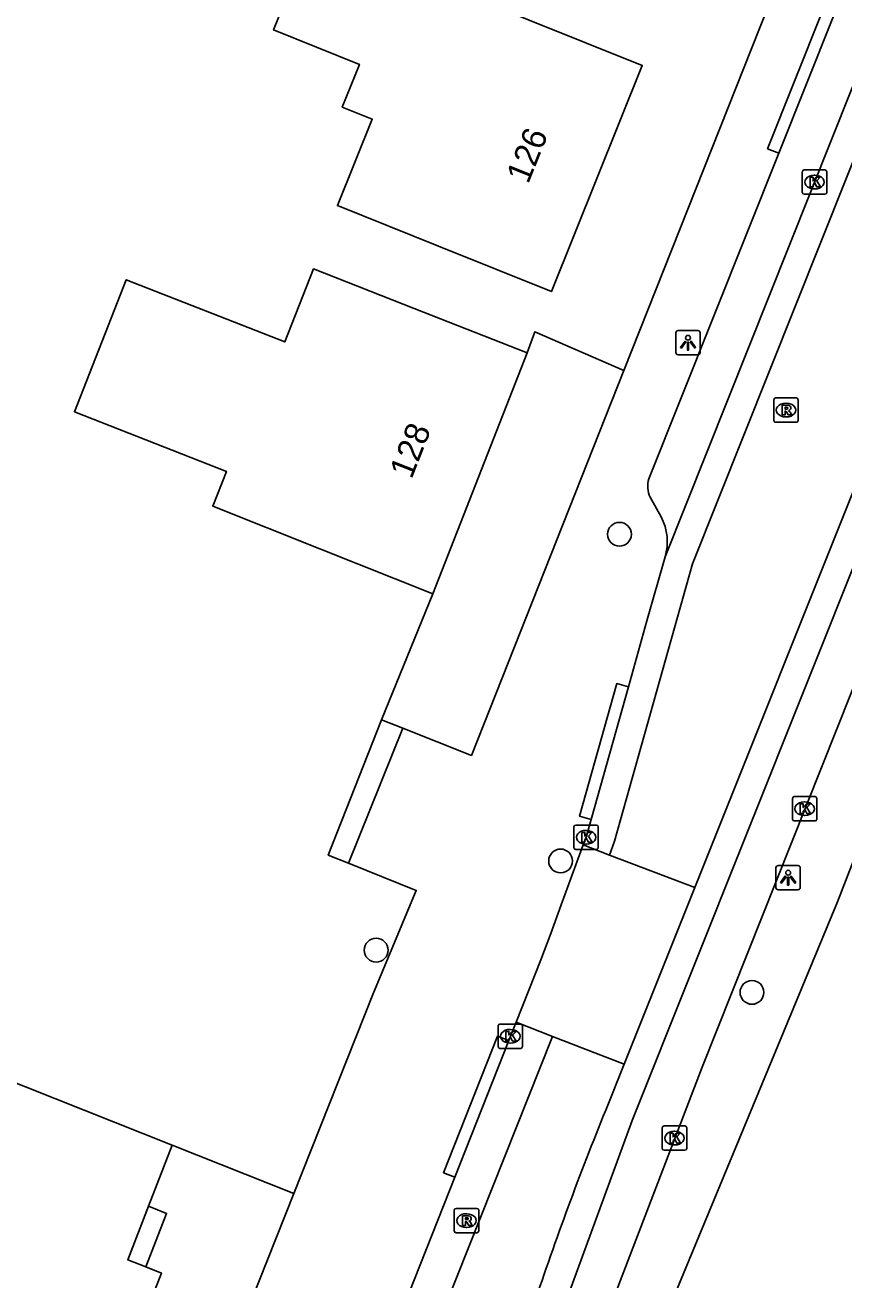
# Model space of a CAD drawing. Extents: x 160026 to 161302, y 384757 to 385701.
# Drawn here: x 160361.4 to 160395, y 384880.6 to 384932.1 of the extents above; entities that cross this region are included whole.
import ezdxf

# ---------------------------------------------------------------- set-up
doc = ezdxf.new("R2010")
doc.units = 0
for name, color, linetype in [('IMGEO_Boom', 7, 'Continuous'), ('IMGEO_Groenvoorziening', 7, 'Continuous'), ('IMGEO_Kolk', 7, 'Continuous'), ('IMGEO_Lichtpunt', 7, 'Continuous'), ('IMGEO_Pand', 7, 'Continuous'), ('IMGEO_Pand_nummerreeks', 7, 'Continuous'), ('IMGEO_Rijbaan_lokaal_open', 7, 'Continuous'), ('IMGEO_Rioolput', 7, 'Continuous'), ('IMGEO_Voetpad_open', 7, 'Continuous')]:
    doc.layers.add(name, color=color, linetype=linetype)

msp = doc.modelspace()

# ---------------------------------------------------------------- linework, layer by layer
at = {"layer": 'IMGEO_Boom'}
for centre in [(160385.821, 384911.173), (160383.404, 384897.757), (160375.826, 384894.095), (160391.266, 384892.363)]:
    msp.add_circle(centre, 0.489, dxfattribs=at)
at = {"layer": 'IMGEO_Groenvoorziening'}
for points in [[(160374.691, 384897.666), (160373.861, 384897.999), (160376.039, 384903.56)], [(160367.44, 384886.086), (160372.439, 384884.099)], [(160366.473, 384883.584), (160367.215, 384883.283), (160366.365, 384881.086)]]:
    msp.add_lwpolyline(points, dxfattribs=at)
at = {"layer": 'IMGEO_Kolk'}
for p, q in [((160393.334, 384925.207), (160393.334, 384926.059)), ((160393.409, 384926.133), (160394.261, 384926.133)), ((160393.822, 384925.913), (160393.847, 384925.913)), ((160394.335, 384926.059), (160394.335, 384925.207)), ((160393.845, 384925.353), (160393.82, 384925.353)), ((160394.261, 384925.133), (160393.409, 384925.133)), ((160392.929, 384899.477), (160392.929, 384900.329)), ((160393.004, 384900.403), (160393.856, 384900.403)), ((160393.417, 384900.183), (160393.442, 384900.183)), ((160393.93, 384900.329), (160393.93, 384899.477)), ((160393.44, 384899.623), (160393.415, 384899.623)), ((160383.952, 384898.306), (160383.952, 384899.158)), ((160384.027, 384899.232), (160384.879, 384899.232)), ((160384.953, 384899.158), (160384.953, 384898.306)), ((160393.856, 384899.403), (160393.004, 384899.403)), ((160384.44, 384899.012), (160384.465, 384899.012)), ((160384.879, 384898.232), (160384.027, 384898.232)), ((160384.463, 384898.452), (160384.438, 384898.452)), ((160380.837, 384890.135), (160380.837, 384890.987)), ((160380.912, 384891.061), (160381.764, 384891.061)), ((160381.325, 384890.841), (160381.35, 384890.841)), ((160381.838, 384890.987), (160381.838, 384890.135)), ((160381.348, 384890.281), (160381.323, 384890.281)), ((160381.764, 384890.061), (160380.912, 384890.061)), ((160387.582, 384885.951), (160387.582, 384886.803)), ((160387.657, 384886.877), (160388.509, 384886.877)), ((160388.07, 384886.657), (160388.095, 384886.657)), ((160388.583, 384886.803), (160388.583, 384885.951)), ((160388.509, 384885.877), (160387.657, 384885.877)), ((160388.093, 384886.097), (160388.068, 384886.097))]:
    msp.add_line(p, q, dxfattribs=at)
for points in [[(160393.334, 384925.207), (160393.334, 384926.059)], [(160393.409, 384926.133), (160394.261, 384926.133)], [(160393.655, 384925.833), (160393.778, 384925.833), (160393.778, 384925.682), (160393.908, 384925.833), (160394.072, 384925.833), (160393.926, 384925.682), (160394.079, 384925.433), (160393.927, 384925.433), (160393.842, 384925.597), (160393.778, 384925.53), (160393.778, 384925.433), (160393.655, 384925.433), (160393.655, 384925.833)], [(160394.335, 384926.059), (160394.335, 384925.207)], [(160394.261, 384925.133), (160393.409, 384925.133)], [(160392.929, 384899.477), (160392.929, 384900.329)], [(160393.004, 384900.403), (160393.856, 384900.403)], [(160393.25, 384900.103), (160393.373, 384900.103), (160393.373, 384899.952), (160393.503, 384900.103), (160393.667, 384900.103), (160393.521, 384899.952), (160393.674, 384899.703), (160393.522, 384899.703), (160393.437, 384899.867), (160393.373, 384899.8), (160393.373, 384899.703), (160393.25, 384899.703), (160393.25, 384900.103)], [(160393.93, 384900.329), (160393.93, 384899.477)], [(160383.952, 384898.306), (160383.952, 384899.158)], [(160384.027, 384899.232), (160384.879, 384899.232)], [(160384.953, 384899.158), (160384.953, 384898.306)], [(160393.856, 384899.403), (160393.004, 384899.403)], [(160384.273, 384898.932), (160384.396, 384898.932), (160384.396, 384898.781), (160384.526, 384898.932), (160384.69, 384898.932), (160384.544, 384898.781), (160384.697, 384898.532), (160384.545, 384898.532), (160384.46, 384898.696), (160384.396, 384898.629), (160384.396, 384898.532), (160384.273, 384898.532), (160384.273, 384898.932)], [(160384.879, 384898.232), (160384.027, 384898.232)], [(160380.837, 384890.135), (160380.837, 384890.987)], [(160380.912, 384891.061), (160381.764, 384891.061)], [(160381.838, 384890.987), (160381.838, 384890.135)], [(160381.158, 384890.761), (160381.281, 384890.761), (160381.281, 384890.61), (160381.411, 384890.761), (160381.575, 384890.761), (160381.429, 384890.61), (160381.582, 384890.361), (160381.43, 384890.361), (160381.345, 384890.525), (160381.281, 384890.458), (160381.281, 384890.361), (160381.158, 384890.361), (160381.158, 384890.761)], [(160381.764, 384890.061), (160380.912, 384890.061)], [(160387.582, 384885.951), (160387.582, 384886.803)], [(160387.657, 384886.877), (160388.509, 384886.877)], [(160388.583, 384886.803), (160388.583, 384885.951)], [(160387.903, 384886.577), (160388.026, 384886.577), (160388.026, 384886.426), (160388.156, 384886.577), (160388.32, 384886.577), (160388.174, 384886.426), (160388.327, 384886.177), (160388.175, 384886.177), (160388.09, 384886.341), (160388.026, 384886.274), (160388.026, 384886.177), (160387.903, 384886.177), (160387.903, 384886.577)], [(160388.509, 384885.877), (160387.657, 384885.877)]]:
    msp.add_lwpolyline(points, dxfattribs=at)
for centre, start, end in [((160393.411, 384926.057), 91.552, 178.448), ((160393.411, 384926.057), 91.552, 178.448), ((160394.259, 384926.057), 1.552, 88.448), ((160394.259, 384926.057), 1.552, 88.448), ((160393.411, 384925.209), 181.552, 268.448), ((160393.411, 384925.209), 181.552, 268.448), ((160394.259, 384925.209), 271.552, 358.448), ((160394.259, 384925.209), 271.552, 358.448), ((160393.006, 384900.327), 91.552, 178.448), ((160393.006, 384900.327), 91.552, 178.448), ((160393.854, 384900.327), 1.552, 88.448), ((160393.854, 384900.327), 1.552, 88.448), ((160384.029, 384899.156), 91.552, 178.448), ((160384.029, 384899.156), 91.552, 178.448), ((160384.877, 384899.156), 1.552, 88.448), ((160384.877, 384899.156), 1.552, 88.448), ((160393.006, 384899.479), 181.552, 268.448), ((160393.006, 384899.479), 181.552, 268.448), ((160393.854, 384899.479), 271.552, 358.448), ((160393.854, 384899.479), 271.552, 358.448), ((160384.029, 384898.308), 181.552, 268.448), ((160384.029, 384898.308), 181.552, 268.448), ((160384.877, 384898.308), 271.552, 358.448), ((160384.877, 384898.308), 271.552, 358.448), ((160380.914, 384890.985), 91.552, 178.448), ((160380.914, 384890.985), 91.552, 178.448), ((160381.762, 384890.985), 1.552, 88.448), ((160381.762, 384890.985), 1.552, 88.448), ((160380.914, 384890.137), 181.552, 268.448), ((160380.914, 384890.137), 181.552, 268.448), ((160381.762, 384890.137), 271.552, 358.448), ((160381.762, 384890.137), 271.552, 358.448), ((160387.659, 384886.801), 91.552, 178.448), ((160387.659, 384886.801), 91.552, 178.448), ((160388.507, 384886.801), 1.552, 88.448), ((160388.507, 384886.801), 1.552, 88.448), ((160387.659, 384885.953), 181.552, 268.448), ((160387.659, 384885.953), 181.552, 268.448), ((160388.507, 384885.953), 271.552, 358.448), ((160388.507, 384885.953), 271.552, 358.448)]:
    msp.add_arc(centre, 0.0765, start, end, dxfattribs=at)
for centre, major_axis, ratio, start_param, end_param in [((160393.821, 384925.633), (-0.387, 0.002), 0.722429, 4.712389, 7.853982), ((160393.846, 384925.633), (-0.39, 0.002), 0.717154, 1.570796, 4.712389), ((160393.416, 384899.903), (-0.387, 0.002), 0.722429, 4.712389, 7.853982), ((160393.441, 384899.903), (-0.39, 0.002), 0.717154, 1.570796, 4.712389), ((160384.439, 384898.732), (-0.387, 0.002), 0.722429, 4.712389, 7.853982), ((160384.464, 384898.732), (-0.39, 0.002), 0.717154, 1.570796, 4.712389), ((160381.324, 384890.561), (-0.387, 0.002), 0.722429, 4.712389, 7.853982), ((160381.349, 384890.561), (-0.39, 0.002), 0.717154, 1.570796, 4.712389), ((160388.069, 384886.377), (-0.387, 0.002), 0.722429, 4.712389, 7.853982), ((160388.094, 384886.377), (-0.39, 0.002), 0.717154, 1.570796, 4.712389)]:
    msp.add_ellipse(centre, major_axis=major_axis, ratio=ratio, start_param=start_param, end_param=end_param, dxfattribs=at)
at = {"layer": 'IMGEO_Lichtpunt'}
for p, q in [((160388.14, 384919.444), (160388.14, 384918.637)), ((160388.14, 384919.444), (160388.14, 384918.637)), ((160389.042, 384919.539), (160388.234, 384919.539)), ((160389.042, 384919.539), (160388.234, 384919.539)), ((160389.136, 384918.637), (160389.136, 384919.444)), ((160389.136, 384918.637), (160389.136, 384919.444)), ((160388.234, 384918.543), (160389.042, 384918.543)), ((160388.234, 384918.543), (160389.042, 384918.543)), ((160392.251, 384897.477), (160392.251, 384896.67)), ((160392.251, 384897.477), (160392.251, 384896.67)), ((160393.153, 384897.572), (160392.345, 384897.572)), ((160393.153, 384897.572), (160392.345, 384897.572)), ((160393.247, 384896.67), (160393.247, 384897.477)), ((160393.247, 384896.67), (160393.247, 384897.477)), ((160392.345, 384896.576), (160393.153, 384896.576)), ((160392.345, 384896.576), (160393.153, 384896.576))]:
    msp.add_line(p, q, dxfattribs=at)
for points in [[(160388.514, 384919.108), (160388.553, 384919.08), (160388.365, 384918.818), (160388.327, 384918.845), (160388.514, 384919.108)], [(160388.616, 384919.06), (160388.663, 384919.06), (160388.663, 384918.738), (160388.616, 384918.738), (160388.616, 384919.06)], [(160388.726, 384919.08), (160388.764, 384919.107), (160388.951, 384918.845), (160388.912, 384918.817), (160388.726, 384919.08)], [(160392.625, 384897.141), (160392.664, 384897.113), (160392.476, 384896.851), (160392.438, 384896.878), (160392.625, 384897.141)], [(160392.727, 384897.093), (160392.774, 384897.093), (160392.774, 384896.771), (160392.727, 384896.771), (160392.727, 384897.093)], [(160392.837, 384897.113), (160392.875, 384897.14), (160393.062, 384896.878), (160393.023, 384896.85), (160392.837, 384897.113)]]:
    msp.add_lwpolyline(points, dxfattribs=at)
for centre in [(160388.639, 384919.242), (160392.75, 384897.275)]:
    msp.add_circle(centre, 0.0994, dxfattribs=at)
for centre, start, end in [((160388.234, 384919.444), 90, 180), ((160388.234, 384919.444), 90, 180), ((160389.042, 384919.444), 0, 90), ((160389.042, 384919.444), 0, 90), ((160388.234, 384918.637), 180, 270), ((160388.234, 384918.637), 180, 270), ((160389.042, 384918.637), 270, 0), ((160389.042, 384918.637), 270, 360), ((160392.345, 384897.477), 90, 180), ((160392.345, 384897.477), 90, 180), ((160393.153, 384897.477), 0, 90), ((160393.153, 384897.477), 0, 90), ((160392.345, 384896.67), 180, 270), ((160392.345, 384896.67), 180, 270), ((160393.153, 384896.67), 270, 0), ((160393.153, 384896.67), 270, 360)]:
    msp.add_arc(centre, 0.0946, start, end, dxfattribs=at)
at = {"layer": 'IMGEO_Pand'}
for points in [[(160263.984, 384964.064), (160263.836, 384964.253), (160268.96, 384968.505), (160269.964, 384967.297), (160273.8, 384969.701), (160275.654, 384966.755), (160321.243, 384894.325), (160329.612, 384881.079), (160331.889, 384879.95), (160336.787, 384880.403), (160344.076, 384881.104), (160348.95, 384881.561), (160350.96, 384883.052), (160354.249, 384891.334), (160367.44, 384886.086)], [(160377.642, 384933.119), (160377.977, 384933.953), (160382.118, 384932.288), (160386.757, 384930.423), (160383.023, 384921.136), (160378.384, 384923.001), (160374.235, 384924.668), (160375.663, 384928.22), (160374.435, 384928.714), (160375.138, 384930.463), (160371.614, 384931.88), (160372.882, 384935.033), (160377.642, 384933.119)], [(160378.152, 384908.732), (160373.507, 384910.581), (160369.114, 384912.329), (160369.673, 384913.752), (160363.432, 384916.203), (160365.562, 384921.626), (160372.073, 384919.069), (160373.253, 384922.072), (160377.383, 384920.45), (160382.036, 384918.622)], [(160378.152, 384908.732), (160382.036, 384918.622)], [(160366.473, 384883.584), (160367.44, 384886.086)], [(160366.365, 384881.086), (160365.62, 384881.379), (160366.473, 384883.584)], [(160362.34, 384870.986), (160363.005, 384870.728), (160367.004, 384880.834), (160366.365, 384881.086)]]:
    msp.add_lwpolyline(points, dxfattribs=at)
at = {"layer": 'IMGEO_Rijbaan_lokaal_open'}
for points in [[(160387.693, 384910.244), (160423.495, 385000), (160443.146, 385049.264)], [(160385.418, 384898), (160385.618, 384898.566), (160388.819, 384909.958), (160424.752, 385000), (160444.248, 385048.841)], [(160448.949, 385047.038), (160436.681, 385016.096), (160430.241, 385000), (160388.913, 384896.667)], [(160382.619, 384876.93), (160386.339, 384887.1), (160431.47, 385000), (160434.346, 385007.194)], [(160387.693, 384910.244), (160386.94, 384907.618), (160386.194, 384904.906)], [(160386.194, 384904.906), (160384.663, 384899.459)], [(160384.663, 384899.459), (160384.45, 384898.732), (160384.332, 384898.414)], [(160381.574, 384891.135), (160382.586, 384893.699), (160383.008, 384894.776), (160383.424, 384895.959), (160384.332, 384898.414)], [(160384.332, 384898.414), (160385.418, 384898)], [(160385.418, 384898), (160388.913, 384896.667)], [(160388.913, 384896.667), (160386.013, 384889.416)], [(160381.277, 384890.383), (160381.574, 384891.135)], [(160383.069, 384890.556), (160381.574, 384891.135)], [(160366.607, 384848.835), (160367.328, 384850.977), (160383.069, 384890.556)], [(160381.277, 384890.383), (160379.059, 384884.775)], [(160386.013, 384889.416), (160383.069, 384890.556)], [(160386.013, 384889.416), (160385.258, 384887.528)], [(160376.702, 384878.824), (160379.059, 384884.775)]]:
    msp.add_lwpolyline(points, dxfattribs=at)
msp.add_arc((160508.642, 384837.412), 133.174, 157.89426, 161.56582, dxfattribs=at)
at = {"layer": 'IMGEO_Rioolput'}
for p, q in [((160392.163, 384915.845), (160392.163, 384916.697)), ((160392.238, 384916.771), (160393.09, 384916.771)), ((160392.651, 384916.551), (160392.676, 384916.551)), ((160393.164, 384916.697), (160393.164, 384915.845)), ((160393.09, 384915.771), (160392.238, 384915.771)), ((160392.674, 384915.991), (160392.649, 384915.991)), ((160379.037, 384882.566), (160379.037, 384883.418)), ((160379.112, 384883.492), (160379.964, 384883.492)), ((160379.525, 384883.272), (160379.55, 384883.272)), ((160380.038, 384883.418), (160380.038, 384882.566)), ((160379.548, 384882.712), (160379.523, 384882.712)), ((160379.964, 384882.492), (160379.112, 384882.492))]:
    msp.add_line(p, q, dxfattribs=at)
for points in [[(160392.163, 384915.845), (160392.163, 384916.697)], [(160392.238, 384916.771), (160393.09, 384916.771)], [(160393.164, 384916.697), (160393.164, 384915.845)], [(160392.752, 384916.469), (160392.5, 384916.471), (160392.5, 384916.071)], [(160392.5, 384916.071), (160392.624, 384916.071), (160392.624, 384916.233), (160392.635, 384916.233)], [(160392.678, 384916.39), (160392.624, 384916.39), (160392.624, 384916.309)], [(160392.624, 384916.309), (160392.676, 384916.309)], [(160392.682, 384916.204), (160392.753, 384916.071), (160392.893, 384916.071), (160392.828, 384916.197)], [(160393.09, 384915.771), (160392.238, 384915.771)], [(160379.037, 384882.566), (160379.037, 384883.418)], [(160379.112, 384883.492), (160379.964, 384883.492)], [(160379.626, 384883.19), (160379.374, 384883.192), (160379.374, 384882.792)], [(160379.552, 384883.111), (160379.498, 384883.111), (160379.498, 384883.03)], [(160380.038, 384883.418), (160380.038, 384882.566)], [(160379.374, 384882.792), (160379.498, 384882.792), (160379.498, 384882.954), (160379.509, 384882.954)], [(160379.498, 384883.03), (160379.55, 384883.03)], [(160379.556, 384882.925), (160379.627, 384882.792), (160379.767, 384882.792), (160379.702, 384882.918)], [(160379.964, 384882.492), (160379.112, 384882.492)]]:
    msp.add_lwpolyline(points, dxfattribs=at)
for centre, radius, start, end in [((160392.24, 384916.695), 0.0765, 91.552, 178.448), ((160392.24, 384916.695), 0.0765, 91.552, 178.448), ((160393.088, 384916.695), 0.0765, 1.552, 88.448), ((160393.088, 384916.695), 0.0765, 1.552, 88.448), ((160392.634, 384916.18), 0.0533, 26.0293, 88.6989), ((160392.66, 384916.498), 0.19, 274.7715, 282.9687), ((160392.684, 384916.294), 0.0964, 77.0061, 93.1865), ((160392.698, 384916.351), 0.0378, 276.6634, 79.6772), ((160392.751, 384916.359), 0.109, 350.3612, 89.416), ((160392.749, 384916.359), 0.112, 277.5842, 350.9817), ((160392.733, 384916.144), 0.108, 29.5134, 73.7905), ((160392.24, 384915.847), 0.0765, 181.552, 268.448), ((160392.24, 384915.847), 0.0765, 181.552, 268.448), ((160393.088, 384915.847), 0.0765, 271.552, 358.448), ((160393.088, 384915.847), 0.0765, 271.552, 358.448), ((160379.114, 384883.416), 0.0765, 91.552, 178.448), ((160379.114, 384883.416), 0.0765, 91.552, 178.448), ((160379.558, 384883.015), 0.0964, 77.0061, 93.1865), ((160379.572, 384883.072), 0.0378, 276.6634, 79.6772), ((160379.625, 384883.08), 0.109, 350.3612, 89.416), ((160379.623, 384883.08), 0.112, 277.5842, 350.9817), ((160379.962, 384883.416), 0.0765, 1.552, 88.448), ((160379.962, 384883.416), 0.0765, 1.552, 88.448), ((160379.114, 384882.568), 0.0765, 181.552, 268.448), ((160379.114, 384882.568), 0.0765, 181.552, 268.448), ((160379.508, 384882.901), 0.0533, 26.0293, 88.6989), ((160379.534, 384883.219), 0.19, 274.7715, 282.9687), ((160379.607, 384882.865), 0.108, 29.5134, 73.7905), ((160379.962, 384882.568), 0.0765, 271.552, 358.448), ((160379.962, 384882.568), 0.0765, 271.552, 358.448)]:
    msp.add_arc(centre, radius, start, end, dxfattribs=at)
for centre, major_axis, ratio, start_param, end_param in [((160392.65, 384916.271), (-0.387, 0.002), 0.722429, 4.712389, 7.853982), ((160392.675, 384916.271), (-0.39, 0.002), 0.717154, 1.570796, 4.712389), ((160379.524, 384882.992), (-0.387, 0.002), 0.722429, 4.712389, 7.853982), ((160379.549, 384882.992), (-0.39, 0.002), 0.717154, 1.570796, 4.712389)]:
    msp.add_ellipse(centre, major_axis=major_axis, ratio=ratio, start_param=start_param, end_param=end_param, dxfattribs=at)
at = {"layer": 'IMGEO_Voetpad_open'}
for points in [[(160386.007, 384917.894), (160418.576, 385000), (160436.61, 385045.463)], [(160392.369, 384926.82), (160391.905, 384927.005), (160394.149, 384932.628), (160394.613, 384932.443)], [(160394.613, 384932.443), (160392.369, 384926.82)], [(160392.369, 384926.82), (160387.031, 384913.444)], [(160404.882, 384922.015), (160403.358, 384918.197), (160394.783, 384896.085), (160382.365, 384866.119)], [(160382.036, 384918.622), (160382.35, 384919.492), (160386.007, 384917.894)], [(160386.007, 384917.894), (160379.738, 384902.09), (160376.921, 384903.209)], [(160399.64, 384915.454), (160389.215, 384889.291), (160385.303, 384879.087)], [(160387.083, 384912.69), (160387.531, 384911.893)], [(160376.039, 384903.56), (160378.152, 384908.732)], [(160384.663, 384899.459), (160384.183, 384899.599), (160385.713, 384905.041), (160386.194, 384904.906)], [(160376.921, 384903.209), (160374.691, 384897.666)], [(160376.039, 384903.56), (160376.921, 384903.209)], [(160372.439, 384884.099), (160375.717, 384892.348), (160377.472, 384896.55), (160374.691, 384897.666)], [(160379.059, 384884.775), (160378.595, 384884.958), (160380.813, 384890.566), (160381.277, 384890.383)], [(160372.439, 384884.099), (160364.181, 384863.317)]]:
    msp.add_lwpolyline(points, dxfattribs=at)
for centre, radius, start, end in [((160387.994, 384913.132), 1.012, 162.0283, 205.8621), ((160385.622, 384910.873), 2.164, 343.1062, 28.1154)]:
    msp.add_arc(centre, radius, start, end, dxfattribs=at)

# ---------------------------------------------------------------- texts
at = {"layer": 'IMGEO_Pand_nummerreeks'}
for s, rotation, p in [('126', 68.0965, (160382.071, 384925.525)), ('128', 68.5591, (160377.279, 384913.403))]:
    msp.add_text(s, height=1, rotation=rotation, dxfattribs=at).set_placement(p)

doc.saveas('drawing.dxf')
